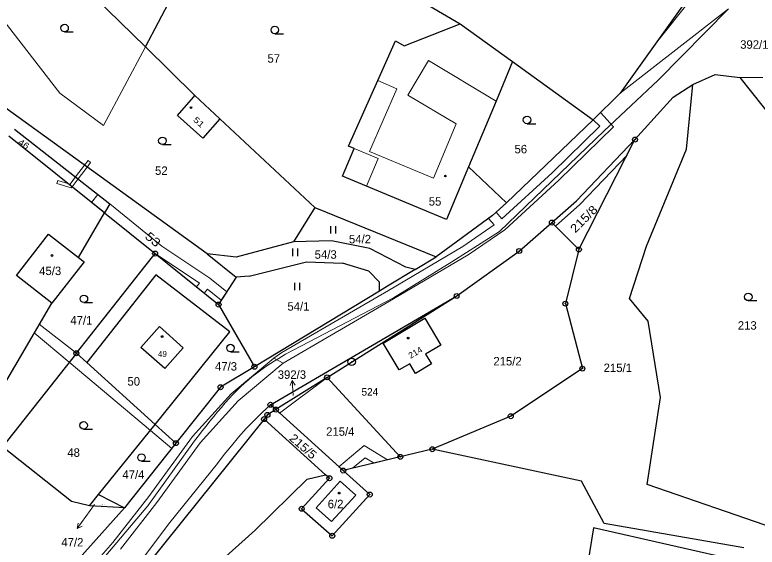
# Model space of a CAD drawing. Extents: x -504006 to -501322, y -1128098 to -1124665.
# Drawn here: x -502824.9 to -502675.9, y -1126704.2 to -1126597.3 of the extents above; entities that cross this region are included whole.
import ezdxf
from ezdxf.enums import TextEntityAlignment as Align

# ---------------------------------------------------------------- set-up
doc = ezdxf.new("R2010")
doc.units = 0
doc.header["$LTSCALE"] = 0.68
for name, color, linetype, lineweight in [('1', 7, 'Continuous', 25), ('13', 7, 'Continuous', 13), ('3', 7, 'Continuous', 25), ('4', 7, 'Continuous', 13), ('5', 7, 'Continuous', 25), ('7', 7, 'Continuous', 13), ('8', 7, 'Continuous', 25)]:
    doc.layers.add(name, color=color, linetype=linetype, lineweight=lineweight)
doc.layers.add('2', color=7, linetype='Continuous')

msp = doc.modelspace()

# ---------------------------------------------------------------- linework, layer by layer
at = {"layer": '1'}
for p, q in [((-502798.68, -1126603.73), (-502780.47, -1126569.42)), ((-502823.75, -1126579.14), (-502798.68, -1126603.73)), ((-502754.26, -1126588.07), (-502735.5, -1126599.1)), ((-502689.51, -1126593.45), (-502703.39, -1126613)), ((-502746.78, -1126603.53), (-502735.5, -1126599.1)), ((-502735.5, -1126599.1), (-502725.01, -1126606.68)), ((-502752.05, -1126610.51), (-502748.49, -1126602.49)), ((-502748.49, -1126602.49), (-502746.78, -1126603.53)), ((-502798.68, -1126603.73), (-502788.73, -1126613.48)), ((-502725.01, -1126606.68), (-502728.33, -1126614.65)), ((-502725.01, -1126606.68), (-502708.83, -1126618.38)), ((-502786.25, -1126645.31), (-502837.36, -1126608.35)), ((-502688.83, -1126611.25), (-502684.35, -1126609.28)), ((-502684.35, -1126609.28), (-502679.44, -1126609.85)), ((-502679.44, -1126609.85), (-502661.24, -1126632.88)), ((-502757.9, -1126623.69), (-502752.05, -1126610.51)), ((-502692.8, -1126613.85), (-502688.83, -1126611.25)), ((-502690.13, -1126624.25), (-502688.83, -1126611.25)), ((-502703.39, -1126613), (-502708.83, -1126618.38)), ((-502792.26, -1126617.51), (-502789.05, -1126613.82)), ((-502789.05, -1126613.82), (-502788.73, -1126613.48)), ((-502788.73, -1126613.48), (-502783.72, -1126618.17)), ((-502700.45, -1126622.34), (-502692.8, -1126613.85)), ((-502728.33, -1126614.65), (-502733.82, -1126627.8)), ((-502787.15, -1126622.05), (-502792.26, -1126617.51)), ((-502783.72, -1126618.17), (-502787.15, -1126622.05)), ((-502783.72, -1126618.17), (-502764.69, -1126635.96)), ((-502708.83, -1126618.38), (-502726.22, -1126635.04)), ((-502824.9, -1126620.25), (-502805.8, -1126635.25)), ((-502806.86, -1126637.06), (-502826.08, -1126621.66)), ((-502712.17, -1126634.67), (-502700.45, -1126622.34)), ((-502711.71, -1126644.41), (-502700.45, -1126622.34)), ((-502759.1, -1126629.67), (-502756.79, -1126624.15)), ((-502756.79, -1126624.15), (-502757.9, -1126623.69)), ((-502698.14, -1126643.72), (-502690.13, -1126624.25)), ((-502733.82, -1126627.8), (-502738.24, -1126638.41)), ((-502726.22, -1126635.04), (-502733.82, -1126627.8)), ((-502754.31, -1126631.7), (-502759.1, -1126629.67)), ((-502738.24, -1126638.41), (-502754.31, -1126631.7)), ((-502805.8, -1126635.25), (-502806.86, -1126637.06)), ((-502726.22, -1126635.04), (-502729.02, -1126637.58)), ((-502717.12, -1126639), (-502712.17, -1126634.67)), ((-502764.69, -1126635.96), (-502768.93, -1126642.89)), ((-502764.69, -1126635.96), (-502740.36, -1126645.9)), ((-502812.1, -1126646.02), (-502806.86, -1126637.06)), ((-502806.86, -1126637.06), (-502796.72, -1126645.22)), ((-502729.02, -1126637.58), (-502740.36, -1126645.9)), ((-502723.66, -1126644.71), (-502717.12, -1126639)), ((-502717.12, -1126639), (-502711.71, -1126644.41)), ((-502818.09, -1126641.33), (-502812.1, -1126646.02)), ((-502768.93, -1126642.89), (-502780.44, -1126645.95)), ((-502761.36, -1126642.69), (-502768.93, -1126642.89)), ((-502753.64, -1126644.2), (-502761.36, -1126642.69)), ((-502746.42, -1126647.93), (-502753.64, -1126644.2)), ((-502701.58, -1126654.27), (-502698.14, -1126643.72)), ((-502798.77, -1126647.81), (-502796.72, -1126645.22)), ((-502796.72, -1126645.22), (-502784, -1126655.46)), ((-502786.25, -1126645.31), (-502780.43, -1126649.96)), ((-502780.44, -1126645.95), (-502786.25, -1126645.31)), ((-502736.22, -1126653.74), (-502723.66, -1126644.71)), ((-502711.71, -1126644.41), (-502714.42, -1126655.28)), ((-502810.97, -1126646.9), (-502817.44, -1126655.15)), ((-502812.1, -1126646.02), (-502810.97, -1126646.9)), ((-502744.52, -1126648.41), (-502740.36, -1126645.9)), ((-502812.52, -1126665.24), (-502798.77, -1126647.81)), ((-502744.52, -1126648.41), (-502750.07, -1126651.77)), ((-502744.52, -1126648.41), (-502746.42, -1126647.93)), ((-502796.55, -1126649.52), (-502810.44, -1126667.12)), ((-502781.75, -1126660.93), (-502796.55, -1126649.52)), ((-502780.43, -1126649.96), (-502784, -1126655.46)), ((-502777.85, -1126649.77), (-502780.43, -1126649.96)), ((-502751.69, -1126652.75), (-502751.7, -1126650.95)), ((-502750.07, -1126651.77), (-502751.69, -1126652.75)), ((-502751.69, -1126652.75), (-502776.79, -1126667.94)), ((-502773.58, -1126675.58), (-502736.22, -1126653.74)), ((-502762.21, -1126670.08), (-502736.22, -1126653.74)), ((-502697.82, -1126658.77), (-502701.58, -1126654.27)), ((-502831.61, -1126679.37), (-502817.44, -1126655.15)), ((-502784, -1126655.46), (-502776.79, -1126667.94)), ((-502714.42, -1126655.28), (-502711.01, -1126668.33)), ((-502695.32, -1126674.11), (-502697.82, -1126658.77)), ((-502799.57, -1126664.06), (-502795.83, -1126659.86)), ((-502795.83, -1126659.86), (-502791.06, -1126664.12)), ((-502796.71, -1126679.52), (-502781.75, -1126660.93)), ((-502747.73, -1126668.59), (-502750.97, -1126663.23)), ((-502739.39, -1126663.59), (-502742.45, -1126665.44)), ((-502812.52, -1126665.24), (-502827.32, -1126684)), ((-502810.44, -1126667.12), (-502812.52, -1126665.24)), ((-502794.8, -1126668.32), (-502799.57, -1126664.06)), ((-502791.06, -1126664.12), (-502794.8, -1126668.32)), ((-502742.45, -1126665.44), (-502741.27, -1126667.39)), ((-502810.44, -1126667.12), (-502796.71, -1126679.52)), ((-502776.79, -1126667.94), (-502783.6, -1126672.06)), ((-502745.64, -1126667.33), (-502747.73, -1126668.59)), ((-502744.45, -1126669.3), (-502745.64, -1126667.33)), ((-502741.27, -1126667.39), (-502744.45, -1126669.3)), ((-502711.01, -1126668.33), (-502725.36, -1126677.88)), ((-502762.21, -1126670.08), (-502772.5, -1126676.55)), ((-502747.53, -1126686.04), (-502762.21, -1126670.08)), ((-502697.98, -1126691.57), (-502695.32, -1126674.11)), ((-502772.5, -1126676.55), (-502773.58, -1126675.58)), ((-502772.5, -1126676.55), (-502774.19, -1126677.62)), ((-502758.98, -1126688.79), (-502772.5, -1126676.55)), ((-502774.86, -1126678.46), (-502806.52, -1126717.92)), ((-502774.19, -1126677.62), (-502774.86, -1126678.46)), ((-502774.86, -1126678.46), (-502762.51, -1126689.64)), ((-502725.36, -1126677.88), (-502741.11, -1126684.5)), ((-502808.06, -1126693.61), (-502796.71, -1126679.52)), ((-502813.5, -1126695.01), (-502827.32, -1126684)), ((-502792.54, -1126683.29), (-502802.89, -1126696.3)), ((-502741.11, -1126684.5), (-502747.53, -1126686.04)), ((-502711.18, -1126690.95), (-502741.11, -1126684.5)), ((-502747.53, -1126686.04), (-502758.98, -1126688.79)), ((-502753.65, -1126693.6), (-502758.98, -1126688.79)), ((-502766.19, -1126690.52), (-502776.7, -1126700.81)), ((-502761.75, -1126690.33), (-502767.32, -1126696.47)), ((-502766.19, -1126690.52), (-502762.51, -1126689.64)), ((-502761.75, -1126690.33), (-502762.51, -1126689.64)), ((-502764.41, -1126696.24), (-502759.58, -1126690.91)), ((-502759.58, -1126690.91), (-502756.48, -1126693.74)), ((-502706.62, -1126699.4), (-502711.18, -1126690.95)), ((-502669.46, -1126701.42), (-502697.98, -1126691.57)), ((-502809.88, -1126695.88), (-502813.5, -1126695.01)), ((-502809.88, -1126695.88), (-502808.06, -1126693.61)), ((-502808.06, -1126693.61), (-502802.89, -1126696.3)), ((-502756.48, -1126693.74), (-502761.31, -1126699.05)), ((-502761.18, -1126701.89), (-502753.65, -1126693.6)), ((-502813.58, -1126708.19), (-502802.89, -1126696.3)), ((-502802.89, -1126696.3), (-502809.88, -1126695.88)), ((-502767.32, -1126696.47), (-502761.18, -1126701.89)), ((-502761.31, -1126699.05), (-502764.41, -1126696.24)), ((-502678.61, -1126704.28), (-502706.62, -1126699.4)), ((-502776.7, -1126700.81), (-502783.12, -1126706.55)), ((-502708.77, -1126700.27), (-502719.18, -1126765.7)), ((-502678.13, -1126707.24), (-502708.77, -1126700.27))]:
    msp.add_line(p, q, dxfattribs=at)
for points in [[(-502817.44, -1126655.15), (-502824.55, -1126649.6), (-502818.09, -1126641.33)], [(-502777.85, -1126649.77), (-502766.33, -1126646.87), (-502759.14, -1126647.12)], [(-502751.7, -1126650.95), (-502753.87, -1126648.78), (-502759.14, -1126647.12)], [(-502750.97, -1126663.23), (-502742.64, -1126658.2), (-502739.39, -1126663.59)], [(-502783.6, -1126672.06), (-502792.54, -1126683.29), (-502796.71, -1126679.52)]]:
    msp.add_lwpolyline(points, dxfattribs=at)
at = {"layer": '13'}
for points in [[(-502689.51, -1126593.45), (-502696.43, -1126603.19), (-502688.95, -1126593.79)], [(-502772.93, -1126666.22), (-502781.43, -1126673.37), (-502789.25, -1126681.94), (-502797.98, -1126694), (-502805.19, -1126703.26), (-502813.13, -1126712.33), (-502839.03, -1126740.37)], [(-502803.65, -1126704.54), (-502796.38, -1126695.2), (-502787.69, -1126683.2), (-502780.05, -1126674.81), (-502771.03, -1126667.24), (-502772.93, -1126666.22)]]:
    msp.add_lwpolyline(points, dxfattribs=at)
for points in [[(-502708.83, -1126618.38), (-502707.51, -1126619.68), (-502717.09, -1126629.04), (-502727.14, -1126638.22), (-502728.27, -1126636.9), (-502729.02, -1126637.58), (-502729.82, -1126638.17), (-502728.7, -1126639.48), (-502735, -1126643.8), (-502749.91, -1126652.61), (-502771.29, -1126665.07), (-502772.93, -1126666.22), (-502771.03, -1126667.24), (-502748.89, -1126654.33), (-502733.92, -1126645.48), (-502726.58, -1126640.45), (-502715.72, -1126630.5), (-502704.73, -1126619.76), (-502707.35, -1126616.91)], [(-502700.45, -1126622.34), (-502712.17, -1126634.67), (-502717.12, -1126639), (-502716.42, -1126639.7), (-502711.5, -1126635.4), (-502702.03, -1126625.44)], [(-502810.18, -1126626.53), (-502810.89, -1126627.49), (-502810.38, -1126627.86), (-502809.66, -1126626.92)], [(-502810.89, -1126627.49), (-502812.67, -1126629.85), (-502812.18, -1126630.24), (-502810.38, -1126627.86)], [(-502813.55, -1126632.06), (-502813.38, -1126631.83), (-502814.24, -1126631.15), (-502816.23, -1126630.58), (-502816.41, -1126631.19)], [(-502812.67, -1126629.85), (-502813.75, -1126631.29), (-502814.24, -1126631.15), (-502813.38, -1126631.83), (-502812.18, -1126630.24)], [(-502809.47, -1126634.97), (-502806.86, -1126637.06), (-502796.72, -1126645.22), (-502787.84, -1126651.19), (-502788.43, -1126651.89), (-502786.87, -1126653.15), (-502786.22, -1126652.37), (-502783.45, -1126654.61), (-502782.36, -1126652.93), (-502785.76, -1126650.17), (-502795.35, -1126643.76), (-502805.8, -1126635.25), (-502808.2, -1126633.36)], [(-502820.96, -1126661.16), (-502813.95, -1126667.05), (-502797.67, -1126680.72), (-502793.37, -1126684.33), (-502792.54, -1126683.29), (-502796.71, -1126679.52), (-502810.44, -1126667.12), (-502812.52, -1126665.24), (-502819.95, -1126659.43)], [(-502762.21, -1126670.08), (-502772.5, -1126676.55), (-502771.74, -1126677.24)], [(-502750.11, -1126686.66), (-502754.76, -1126683.79), (-502759.84, -1126688.01), (-502758.98, -1126688.79), (-502757.11, -1126688.34), (-502754.59, -1126686.25), (-502752.79, -1126687.3)]]:
    msp.add_lwpolyline(points, close=True, dxfattribs=at)
at = {"layer": '3'}
for p, q in [((-502814.883, -1126600.7), (-502813.133, -1126600.7)), ((-502772.713, -1126601.08), (-502770.963, -1126601.08)), ((-502722.103, -1126619.15), (-502720.353, -1126619.15)), ((-502795.263, -1126623.33), (-502793.513, -1126623.33)), ((-502761.471, -1126641.21), (-502761.471, -1126639.71)), ((-502760.47, -1126641.21), (-502760.47, -1126639.71)), ((-502769.111, -1126645.73), (-502769.111, -1126644.23)), ((-502768.11, -1126645.73), (-502768.11, -1126644.23)), ((-502768.671, -1126652.6), (-502768.671, -1126651.1)), ((-502767.67, -1126652.6), (-502767.67, -1126651.1)), ((-502677.723, -1126654.68), (-502675.973, -1126654.68)), ((-502811.003, -1126655.07), (-502809.253, -1126655.07)), ((-502781.593, -1126664.94), (-502779.843, -1126664.94)), ((-502811.063, -1126680.46), (-502809.313, -1126680.46)), ((-502799.453, -1126686.91), (-502797.703, -1126686.91))]:
    msp.add_line(p, q, dxfattribs=at)
for centre in [(-502814.8829, -1126599.9498), (-502772.7129, -1126600.3298), (-502722.1029, -1126618.3998), (-502795.2629, -1126622.5798), (-502677.7229, -1126653.9298), (-502811.0029, -1126654.3198), (-502781.5929, -1126664.1898), (-502811.0629, -1126679.7098), (-502799.4529, -1126686.1598)]:
    msp.add_circle(centre, 0.75, dxfattribs=at)
at = {"layer": '4'}
for p, q in [((-502703.39, -1126613), (-502681.67, -1126596.09)), ((-502681.67, -1126596.09), (-502695.8, -1126610.4)), ((-502827.48, -1126597.97), (-502815.83, -1126613)), ((-502807.06, -1126619.54), (-502798.68, -1126603.73)), ((-502746, -1126613.4), (-502741.9, -1126606.47)), ((-502741.9, -1126606.47), (-502728.33, -1126614.65)), ((-502674.8, -1126609.85), (-502679.44, -1126609.85)), ((-502752.05, -1126610.51), (-502748.25, -1126612.18)), ((-502695.8, -1126610.4), (-502706.6, -1126620.6)), ((-502815.83, -1126613), (-502807.06, -1126619.54)), ((-502748.25, -1126612.18), (-502753.74, -1126624.73)), ((-502736.31, -1126619.16), (-502746, -1126613.4)), ((-502740.87, -1126630.12), (-502736.31, -1126619.16)), ((-502706.6, -1126620.6), (-502727.6, -1126640.8)), ((-502751.99, -1126626.16), (-502756.79, -1126624.15)), ((-502753.74, -1126624.73), (-502740.87, -1126630.12)), ((-502754.31, -1126631.7), (-502751.99, -1126626.16)), ((-502727.6, -1126640.8), (-502737.2, -1126646.9)), ((-502737.2, -1126646.9), (-502748.9, -1126654.1)), ((-502748.9, -1126654.1), (-502770.55, -1126665.4)), ((-502788.8, -1126682.8), (-502798.2, -1126695.9)), ((-502793.8, -1126699.2), (-502784.2, -1126687.4)), ((-502798.2, -1126695.9), (-502812.6, -1126712.9)), ((-502806.8, -1126716.5), (-502793.8, -1126699.2))]:
    msp.add_line(p, q, dxfattribs=at)
for points in [[(-502770.55, -1126665.4), (-502771.298, -1126665.861), (-502772.055, -1126666.332), (-502772.804, -1126666.804), (-502773.553, -1126667.287), (-502774.311, -1126667.79), (-502775.061, -1126668.306), (-502775.812, -1126668.844), (-502776.572, -1126669.413), (-502777.325, -1126670.005), (-502778.079, -1126670.63), (-502778.843, -1126671.299), (-502779.6, -1126672), (-502780.358, -1126672.743), (-502781.127, -1126673.536), (-502781.888, -1126674.355), (-502782.65, -1126675.208), (-502783.422, -1126676.1), (-502784.186, -1126677.006), (-502784.951, -1126677.935), (-502785.725, -1126678.893), (-502786.491, -1126679.854), (-502787.258, -1126680.826), (-502788.033, -1126681.817), (-502788.8, -1126682.8)], [(-502784.2, -1126687.4), (-502782.842, -1126685.576), (-502781.428, -1126683.794), (-502779.961, -1126682.057), (-502778.441, -1126680.365), (-502776.87, -1126678.721), (-502775.249, -1126677.125), (-502773.58, -1126675.58)]]:
    msp.add_lwpolyline(points, dxfattribs=at)
at = {"layer": '5'}
for centre in [(-502789.5268, -1126615.9192), (-502738.4968, -1126629.6592), (-502817.3968, -1126645.6092), (-502795.3168, -1126661.8892), (-502745.9368, -1126662.1992), (-502759.7868, -1126693.3092)]:
    msp.add_circle(centre, 0.175, dxfattribs=at)
at = {"layer": '7'}
for p, q in [((-502769.219, -1126670.696), (-502769.649, -1126671.73)), ((-502812.374, -1126700.448), (-502811.38, -1126699.932))]:
    msp.add_line(p, q, dxfattribs=at)
for points in [[(-502769.01, -1126673.69), (-502769.219, -1126670.696), (-502768.65, -1126671.66)], [(-502808.86, -1126695.59), (-502810.61, -1126698.02), (-502812.374, -1126700.448), (-502812.19, -1126699.343)]]:
    msp.add_lwpolyline(points, dxfattribs=at)
at = {"layer": '8'}
for centre, radius in [((-502700.45, -1126622.3399), 0.5), ((-502700.45, -1126622.3399), 0.0303), ((-502717.12, -1126638.9999), 0.5), ((-502717.12, -1126638.9999), 0.0303), ((-502723.66, -1126644.7099), 0.5), ((-502711.71, -1126644.4099), 0.5), ((-502711.71, -1126644.4099), 0.0303), ((-502796.72, -1126645.2199), 0.5), ((-502796.72, -1126645.2199), 0.0303), ((-502723.66, -1126644.7099), 0.0303), ((-502736.22, -1126653.7399), 0.5), ((-502736.22, -1126653.7399), 0.0303), ((-502714.42, -1126655.2799), 0.5), ((-502784, -1126655.4599), 0.5), ((-502784, -1126655.4599), 0.0303), ((-502714.42, -1126655.2799), 0.0303), ((-502812.52, -1126665.2399), 0.5), ((-502812.52, -1126665.2399), 0.0303), ((-502757.29, -1126666.9598), 0.75), ((-502776.79, -1126667.9399), 0.5), ((-502776.79, -1126667.9399), 0.0303), ((-502757.29, -1126666.9598), 0.03), ((-502711.01, -1126668.3299), 0.5), ((-502762.21, -1126670.0799), 0.5), ((-502711.01, -1126668.3299), 0.0303), ((-502762.21, -1126670.0799), 0.0303), ((-502783.6, -1126672.0599), 0.5), ((-502783.6, -1126672.0599), 0.0303), ((-502773.58, -1126675.5799), 0.5), ((-502773.58, -1126675.5799), 0.0303), ((-502774.19, -1126677.6199), 0.5), ((-502772.5, -1126676.5499), 0.5), ((-502772.5, -1126676.5499), 0.0303), ((-502774.86, -1126678.4599), 0.5), ((-502774.86, -1126678.4599), 0.0303), ((-502774.19, -1126677.6199), 0.0303), ((-502725.36, -1126677.8799), 0.5), ((-502725.36, -1126677.8799), 0.0303), ((-502792.54, -1126683.2899), 0.5), ((-502792.54, -1126683.2899), 0.0303), ((-502741.11, -1126684.4999), 0.5), ((-502741.11, -1126684.4999), 0.0303), ((-502747.53, -1126686.0399), 0.5), ((-502747.53, -1126686.0399), 0.0303), ((-502758.98, -1126688.7899), 0.5), ((-502758.98, -1126688.7899), 0.0303), ((-502761.75, -1126690.3299), 0.5), ((-502761.75, -1126690.3299), 0.0303), ((-502753.65, -1126693.5999), 0.5), ((-502753.65, -1126693.5999), 0.0303), ((-502767.32, -1126696.4699), 0.5), ((-502767.32, -1126696.4699), 0.0303), ((-502761.18, -1126701.8899), 0.5), ((-502761.18, -1126701.8899), 0.0303)]:
    msp.add_circle(centre, radius, dxfattribs=at)

# ---------------------------------------------------------------- texts
at = {"layer": '2'}
for s, p in [('392/1', (-502679.35, -1126604.105)), ('215/2', (-502728.86, -1126667.685)), ('215/1', (-502706.74, -1126669.015))]:
    msp.add_text(s, height=1.7, dxfattribs=at).set_placement(p)
for s, height, p in [('57', 1.7, (-502772.919, -1126606.905)), ('56', 1.7, (-502723.359, -1126625.105)), ('52', 1.7, (-502795.469, -1126629.425)), ('55', 1.7, (-502740.559, -1126635.605)), ('54/2', 1.7, (-502755.619, -1126643.175)), ('54/3', 1.7, (-502762.499, -1126646.265)), ('45/3', 1.7, (-502817.769, -1126649.545)), ('54/1', 1.7, (-502767.969, -1126656.685)), ('47/1', 1.7, (-502811.519, -1126659.475)), ('213', 1.7, (-502677.929, -1126660.505)), ('49', 1.2, (-502795.249, -1126665.97)), ('47/3', 1.7, (-502782.499, -1126668.725)), ('392/3', 1.7, (-502769.28, -1126670.375)), ('50', 1.7, (-502801.009, -1126671.735)), ('215/4', 1.7, (-502759.57, -1126681.805)), ('48', 1.7, (-502813.069, -1126686.035)), ('47/4', 1.7, (-502801.069, -1126690.445)), ('6/2', 1.7, (-502760.51, -1126696.355)), ('47/2', 0.2, (-502807.179, -1126695.77))]:
    msp.add_text(s, height=height, dxfattribs=at).set_placement(p, align=Align.CENTER)
for s, height, rotation, width, p in [('51', 1.2, 318, 1.3, (-502788.3465, -1126619.2863)), ('46', 1.244, 327, 1.2, (-502823.4168, -1126623.7625)), ('215/8', 1.7, 45, 1.15, (-502710.1125, -1126638.8935)), ('53', 1.7, 320, 1.25, (-502797.7039, -1126643.029)), ('214', 1.2, 31, 1.1, (-502744.2075, -1126665.612)), ('215/5', 1.7, 319, 1.1, (-502767.5846, -1126684.5775))]:
    msp.add_text(s, height=height, rotation=rotation, dxfattribs=dict(at, width=width)).set_placement(p, align=Align.CENTER)
msp.add_text('47/2', height=1.7, dxfattribs=at).set_placement((-502811.109, -1126704.035), align=Align.RIGHT)
at = {"layer": '8'}
msp.add_text('524', height=1.5, dxfattribs=at).set_placement((-502751.969, -1126673.745), align=Align.RIGHT)

doc.saveas('drawing.dxf')
